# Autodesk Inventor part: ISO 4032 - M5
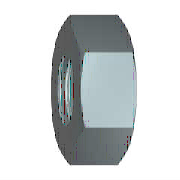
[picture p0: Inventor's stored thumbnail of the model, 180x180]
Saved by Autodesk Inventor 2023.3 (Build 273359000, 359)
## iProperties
IsCustomPart: 0
Created: 2022-02
Part Number: ISO 4032 - M5
Material: Acier inoxydable 440C
Description: Ecrous hexagonaux - Style 1 - Produits de classes A et B
Document SubType Name: Modeling
Standard: ISO 4032
Designer: Thier
Standards Organization: AFNOR
Language: fr-FR
Size Designation: M5
Categories: <MemberInstance><Categories><Category DisplayName="Visserie" InternalName="e4da775c-781d-43d5-af7c-5136215cf5a6" Mnemonic="FSTN"><Category DisplayName="Ecrous"
Density: 7.75 g/cm^3
Appearance: Semi-poli
Author: Thier
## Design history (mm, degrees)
sketch "Esquisse1"
  geometry: L1 (-4.619, 0)-(-2.309, 4); L2 (-2.309, 4)-(2.309, 4); L3 (2.309, 4)-(4.619, 0); L4 (4.619, 0)-(2.309, -4); L5 (2.309, -4)-(-2.309, -4); L6 (-2.309, -4)-(-4.619, 0); 2 further points
  constraints: 12 end point, 1 coincident, 1 horizontal, 11 other
  dimensions: "d0" = 9.2376 distance of L3.end L1.start (= 1.1547 x SW)
extrude "Corps" new body sketch "Esquisse1" distance "d1" = 4.7 (= KOH); taper "d2" = 0 deg
sketch "Esquisse2"
  geometry: L1 (0, 2.309)-(0, 4.619) reference; L2 (0, 4.619)-(4.7, 4.619) reference; L3 (4.7, 2.309)-(4.7, 4.619) reference; L4 (-0.94, 0)-(5.64, 0) reference; L5 (0.357, 4.619)-(0, 4); L6 (4.343, 4.619)-(4.7, 4)
  constraints: 4 end point, 4 point on line
  dimensions: "d3" = 30 deg angle of L1 L5 (= ANG1); "d4" = 30 deg angle of L3 L6 (= ANG2); "d5" = 8 diameter of L5.end L4 (= SW0); "d6" = 8 diameter of L6.end L4 (= SW01)
revolve "Chanfrein1" sketch "Esquisse2" stored, may be unused: angle "d7" = 90 deg
sketch "Esquisse3"
  geometry: A1 r 4 centre (0, 0) between (-2, -3.464) and (2, -3.464) reference; 1 further point
  constraints: 1 coincident
hole "Filetage" sketch "Esquisse3" at (0, 0) diameter "d25" = 4.134; stored, may be unused: countersink angle "d29" = 82 deg, drill point angle "d31" = 118 deg; dims "d26" = 6, "d27" = 4, "d28" = 2, "d30" = 8
workaxis "Work Axis1"
workplane "Work Plane1"
body "Solid1"
chamfer "Chanfrein2" distance "d8" = 0.43301 (= -0.5 x GD1 + 0.5 x NND); stored, may be unused: angle "d9" = 30 deg, second distance "d40" = 0.43301 (= -0.5 x GD1 + 0.5 x NND)
chamfer "Chanfrein3" distance "d10" = 0.43301 (= -0.5 x GD1 + 0.5 x NND); stored, may be unused: angle "d11" = 30 deg, second distance "d41" = 0.43301 (= -0.5 x GD1 + 0.5 x NND)
other parameters: "ANG1" = 30 deg [user parameter; used in 1 equation term], "ANG2" = 30 deg [user parameter; used in 1 equation term], "NND" = 5 [user parameter; used in 4 equation terms], "KOH" = 4.7 [user parameter; used in 1 equation term], "SW" = 8 [user parameter; used in 2 equation terms], "SW0" = 8 [user parameter; used in 2 equation terms], "SW01" = 8 (= SW0) [user parameter; used in 1 equation term], "GD1" = 4.13397 (computed from THREADDIA, PTC, TOA) [user parameter; used in 4 equation terms], "d13" = 0, "d14" = 0, "d39" = 0, "d42" = 0, "GUL" = 0.43301 (= 0.541266 x PTC) [user parameter], "TPU" = 12.5 (computed from PTC) [user parameter], "THREADDIA" = 5 [user parameter; used in 1 equation term], "TOA" = 30 deg [user parameter; used in 1 equation term], "PTC" = 0.8 [user parameter; used in 4 equation terms], "E0" = 9.24 (= 1.155 x SW) [user parameter], "GAL" = 0.43301 (= 0.541266 x PTC) [user parameter]
